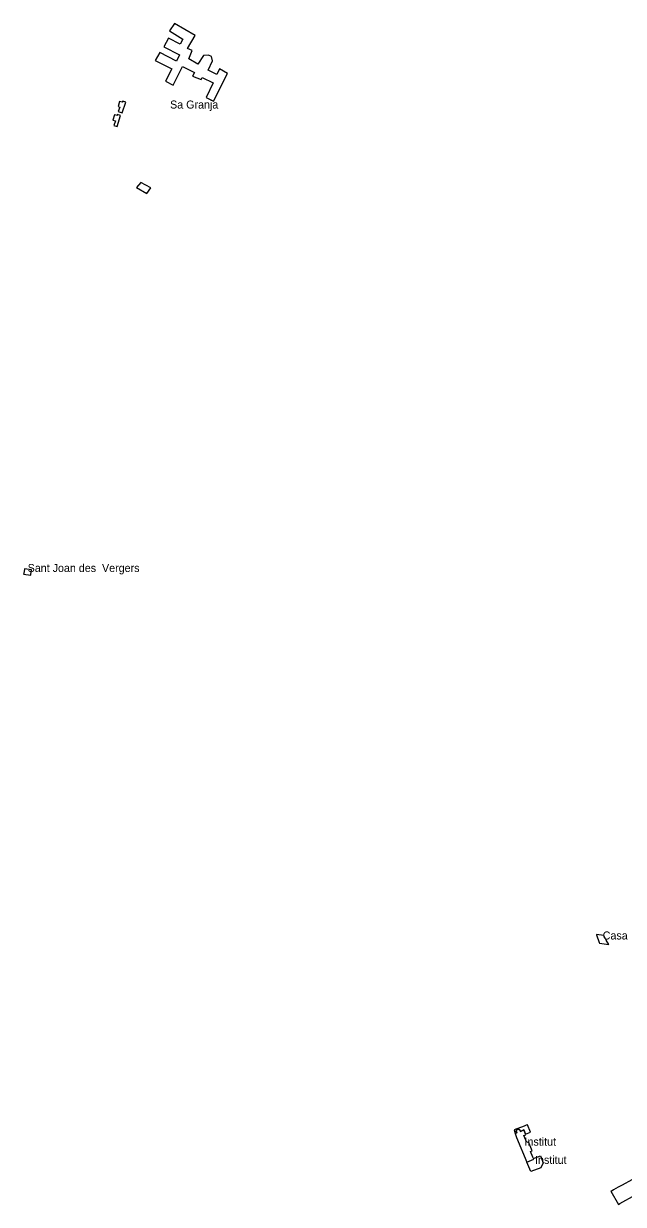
# Model space of a CAD drawing. Extents: x 599451 to 612034, y 4411179 to 4428219.
# Drawn here: x 606529 to 607428, y 4415934 to 4417704 of the extents above; entities that cross this region are included whole.
import ezdxf

# ---------------------------------------------------------------- set-up
doc = ezdxf.new("R2010")
doc.units = 0
for name, color, linetype in [('Bé Arquitectònic', 7, 'Continuous'), ('Element patrimoni', 7, 'Continuous'), ('Elements patrimoni', 7, 'Continuous'), ('Elements patrimonials', 7, 'Continuous')]:
    doc.layers.add(name, color=color, linetype=linetype)

msp = doc.modelspace()

# ---------------------------------------------------------------- linework, layer by layer
at = {"layer": 'Bé Arquitectònic'}
for points in [[(606754.8, 4417704.1), (606747.6, 4417693.2), (606767.5, 4417680.9), (606763.7, 4417673.3), (606745.9, 4417682.2), (606738.8, 4417669.1), (606762.4, 4417657.3), (606757.8, 4417647.6), (606732.9, 4417660.7), (606726.1, 4417648.9), (606751, 4417636.2), (606741.3, 4417617.6), (606753.1, 4417611.7), (606767, 4417639.6), (606785.2, 4417630.7), (606782.2, 4417625.2), (606794.9, 4417620.2), (606796.6, 4417623.5), (606813, 4417615.5), (606802.5, 4417593.6), (606813.4, 4417587.7), (606834.5, 4417629.4), (606822.7, 4417636.2), (606818.5, 4417627.8), (606805.4, 4417634.5), (606812.2, 4417648.4), (606810.5, 4417654.8), (606805.8, 4417656.9), (606798.7, 4417656.5), (606790.2, 4417643.4), (606776.3, 4417651.4), (606781.4, 4417663.6), (606774.6, 4417666.6), (606786, 4417686.4)], [(606676.4, 4417570.3), (606682, 4417586.2), (606677.4, 4417587.9), (606676.4, 4417586.2), (606672.7, 4417587.3), (606670.5, 4417580.1), (606672.8, 4417579.1), (606670.3, 4417572.5)], [(606664, 4417551.6), (606668.9, 4417550), (606674.1, 4417566.5), (606669.2, 4417568.1), (606668.9, 4417566.2), (606665.1, 4417567.3), (606662.3, 4417559.6), (606666.4, 4417558.3)], [(606698, 4417458.4), (606713.6, 4417449.4), (606719.7, 4417457.7), (606704.6, 4417465.8)], [(606539.7, 4416878.4), (606540.8, 4416885.2), (606530, 4416886.9), (606530, 4416886.4), (606528.9, 4416879.7), (606528.7, 4416878.7), (606539.5, 4416877)]]:
    msp.add_lwpolyline(points, close=True, dxfattribs=at)
at = {"layer": 'Element patrimoni'}
msp.add_lwpolyline([(607293.2, 4416002.7), (607295.8, 4416003.7), (607295.9, 4416003.5), (607303.6, 4416006.4), (607307.8, 4415996.1), (607304.2, 4415988.8), (607289.5, 4415982.9), (607283.3, 4415997.1), (607293.7, 4416001.4), (607293.2, 4416002.7)], close=True, dxfattribs=at)
at = {"layer": 'Elements patrimoni'}
for points in [[(607281.3, 4416038.9), (607288.9, 4416042.1), (607284.3, 4416053.2), (607282.5, 4416052.6), (607279.1, 4416051.2), (607264.5, 4416045.5), (607265.9, 4416040.2), (607268.1, 4416041), (607267.1, 4416043.4), (607267.7, 4416043.7), (607267.7, 4416044.3), (607267.8, 4416044.8), (607268, 4416045.3), (607268.3, 4416045.8), (607268.7, 4416046.2), (607269.2, 4416046.5), (607269.7, 4416046.6), (607270.3, 4416046.6), (607270.8, 4416046.5), (607271.3, 4416046.3), (607271.8, 4416046), (607272.1, 4416045.6), (607272.1, 4416045.5), (607272.7, 4416045.7), (607272.7, 4416045.7), (607273.6, 4416043.3), (607278.6, 4416045.4)], [(607462.5, 4415982.6), (607459.8, 4415981.1), (607456.9, 4415979.5), (607452.7, 4415977.2), (607446.4, 4415973.7), (607440.7, 4415970.5), (607426.2, 4415962.7), (607420.4, 4415959.5), (607413.2, 4415955.5), (607411.1, 4415954.3), (607409.5, 4415953.4), (607420.7, 4415933.8), (607422.9, 4415935), (607446.5, 4415948.2), (607448.6, 4415949.4), (607475.4, 4415964), (607472.6, 4415968), (607469.7, 4415972.1), (607465.4, 4415978.5)]]:
    msp.add_lwpolyline(points, close=True, dxfattribs=at)
at = {"layer": 'Elements patrimonials'}
for points in [[(607387.9, 4416338.6), (607387.8, 4416338.2), (607391.8, 4416326.4), (607392.1, 4416325.6), (607406.4, 4416323.4), (607402.5, 4416330.2), (607398.6, 4416336.9)], [(607283.3, 4415997.1), (607293.7, 4416001.4), (607293.2, 4416002.7), (607292.5, 4416004.5), (607288.9, 4416013.3), (607291.1, 4416014.2), (607285.8, 4416027.4), (607283.5, 4416026.4), (607279, 4416037.2), (607281.6, 4416038.3), (607278.6, 4416045.4), (607273.6, 4416043.3), (607272.7, 4416045.7), (607272.1, 4416045.6), (607271.8, 4416046), (607271.3, 4416046.3), (607270.8, 4416046.5), (607270.3, 4416046.6), (607269.7, 4416046.6), (607269.2, 4416046.5), (607268.7, 4416046.2), (607268.3, 4416045.8), (607268, 4416045.4), (607268, 4416045.3), (607267.8, 4416044.8), (607267.7, 4416044.3), (607267.7, 4416043.7), (607267.1, 4416043.4), (607268.1, 4416041), (607265.9, 4416040.2), (607268, 4416034.1)]]:
    msp.add_lwpolyline(points, close=True, dxfattribs=at)

# ---------------------------------------------------------------- texts
at = {"layer": 'Bé Arquitectònic'}
for s, p in [('Sa Granja', (606748.4, 4417576.8)), ('Sant Joan des  Vergers', (606534.8, 4416882))]:
    msp.add_text(s, height=12, dxfattribs=at).set_placement(p)
at = {"layer": 'Element patrimoni'}
msp.add_text('Institut', height=12, dxfattribs=at).set_placement((607295.6, 4415994.6))
at = {"layer": 'Elements patrimonials'}
for s, p in [('Casa   31', (607397.1, 4416331)), ('Institut', (607279.8, 4416021.9))]:
    msp.add_text(s, height=12, dxfattribs=at).set_placement(p)

doc.saveas('drawing.dxf')
